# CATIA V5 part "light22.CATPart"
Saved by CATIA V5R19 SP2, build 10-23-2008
Part number: light22
Bounding box of the stored display mesh (mm): x -1176.042 to -853.11, y -549.702 to 549.702, z 615.104 to 666.171
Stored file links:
  C:\BEHROOZ\catia learning\tarh haye mashin\hb\light22.CATPart
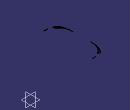
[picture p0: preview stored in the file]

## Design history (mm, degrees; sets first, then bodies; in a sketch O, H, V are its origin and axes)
Body1 (main body)
  DatumSurface1
  ThickSurface1: Surface DatumSurface1, TopOffset 8, BotOffset -5
  DatumSurface2
  Plane1: stored without definition
  ThickSurface2: Surface DatumSurface2, TopOffset 8, BotOffset -5
  Sketch1 on Plane1, origin (-1447, 0, 0), H (0, 1, 0), V (0, 0, 1)
    arc A1 centre (-542.0349, -1967.8124) radius 2634.209 from (-315.0255, 656.5969) to (-507.5187, 666.1705) ccw
    line L1 (-509.9756, 658.0818) -> (-492.0125, 646.398)
    arc A2 centre (-508.6045, 1761.4129) radius 1126.0789 from (-455.7926, 636.5731) to (-314.8319, 652.1313) ccw
    arc A3 centre (-458.6613, 697.6735) radius 61.1677 from (-455.7926, 636.5731) to (-492.0125, 646.398) cw
    arc A4 centre (-507.5764, 661.7705) radius 4.4004 from (-507.5187, 666.1705) to (-509.9756, 658.0818) ccw
    arc A5 centre (-315.2197, 654.3515) radius 2.2538 from (-315.0255, 656.5969) to (-314.8319, 652.1313) cw
    arc A6 centre (542.0349, -1967.8124) radius 2634.209 from (315.0255, 656.5969) to (507.5187, 666.1705) cw
    line L2 (509.9756, 658.0818) -> (492.0125, 646.398)
    arc A7 centre (508.6045, 1761.4129) radius 1126.0789 from (455.7926, 636.5731) to (314.8319, 652.1313) cw
    arc A8 centre (458.6613, 697.6735) radius 61.1677 from (455.7926, 636.5731) to (492.0125, 646.398) ccw
    arc A9 centre (507.5764, 661.7705) radius 4.4004 from (507.5187, 666.1705) to (509.9756, 658.0818) cw
    arc A10 centre (315.2197, 654.3515) radius 2.2538 from (315.0255, 656.5969) to (314.8319, 652.1313) ccw
    unspec C1
    unspec C2
    unspec C3
    unspec C4
    unspec C5
    unspec C6
    unspec C7
    unspec C8
    unspec C9
  Pocket1: profile Sketch1, direction (-1, 0, 0), length -714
